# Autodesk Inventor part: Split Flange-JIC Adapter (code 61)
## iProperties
Category: Hydraulics
Title: Split Flange-JIC Adapter (code 61)
Author: QBZ
Comments: O'rings for Split Flange .120 dia (TYP)
Shininess: 27.0
PropertySet Name: _Private Model Information
Created: 2001-03
Part Number: 500025-12S
Document SubType Name: Modeling
Designer: QBZ
Catalog Web Link: http://www.aeroquip.com
Description: Tube Adapter, Split Flange JIC 12-12 Straight
Material: Steel, Mild
Control State: 0
Master: False
Checked Out: False
PropertySet Name: Design Tracking Control
Density: 7.86
Volumn: 23.109022760693517
Area: 90.10290210904132
PropertySet Name: Model Information
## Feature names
1. Revolution1
2. Wrench Flat [Extrusion]
